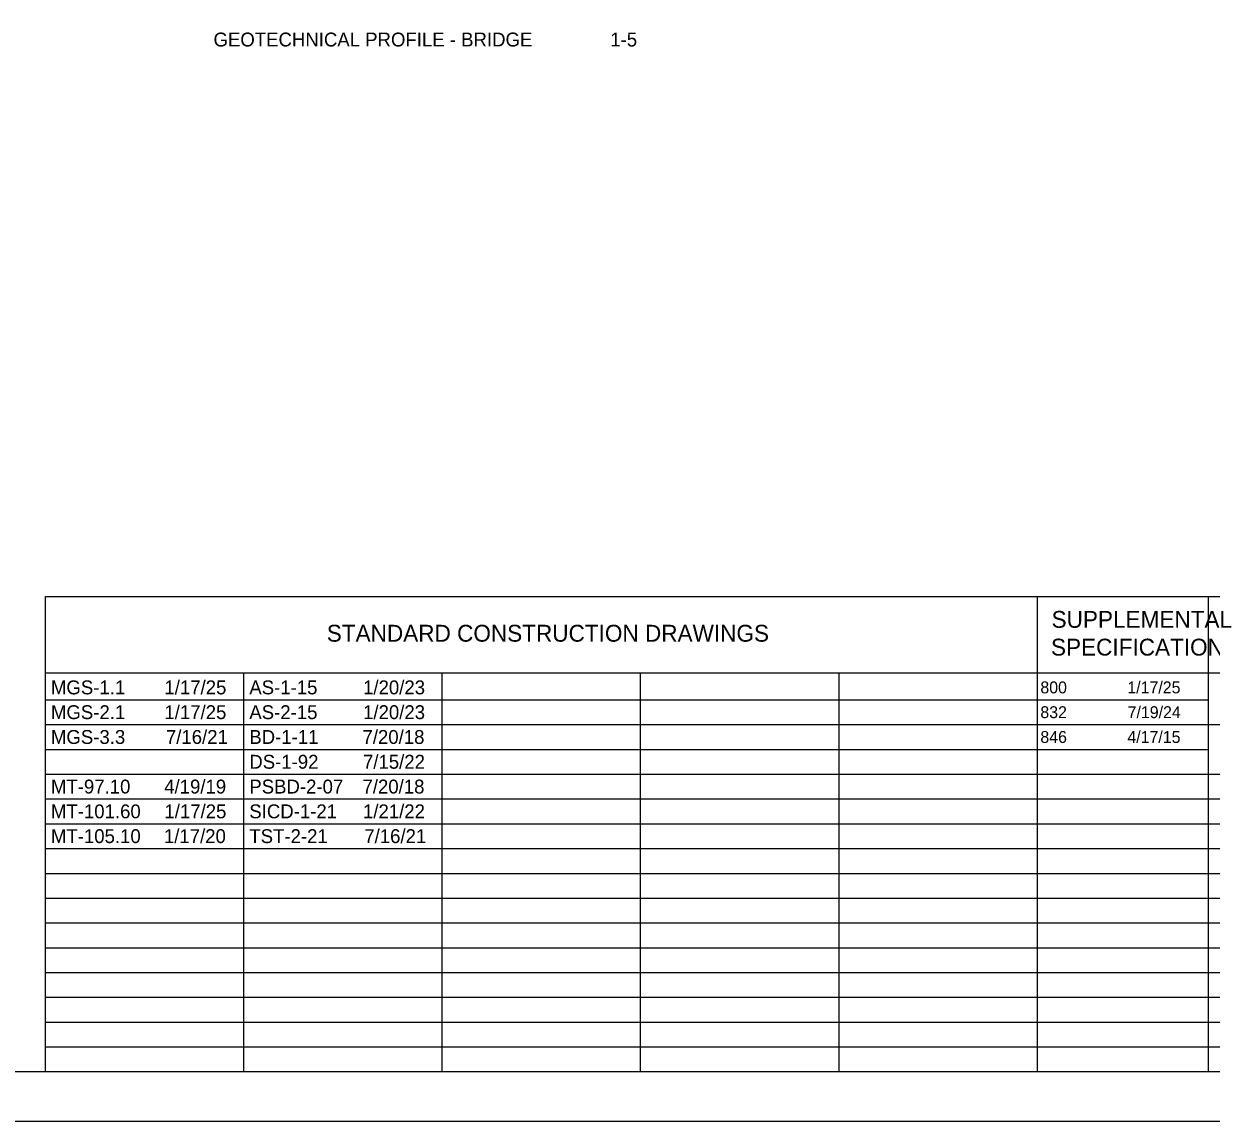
# Model space of a CAD drawing. Extents: x 0 to 34, y 0 to 22.
# Drawn here: x 9.93 to 21.9, y 0 to 11.07 of the extents above; entities that cross this region are included whole.
import ezdxf

# ---------------------------------------------------------------- set-up
doc = ezdxf.new("R2010")
doc.units = 0
for name, color, linetype in [('SH_Border', 7, 'Continuous'), ('SH_Cut_Line', 7, 'Continuous'), ('SH_Data', 7, 'Continuous'), ('SH_Text', 7, 'Continuous')]:
    doc.layers.add(name, color=color, linetype=linetype)

msp = doc.modelspace()

# ---------------------------------------------------------------- linework, layer by layer
at = {"layer": 'SH_Border'}
msp.add_lwpolyline([(1.5, 21.5), (33.5, 21.5), (33.5, 0.5), (1.5, 0.5)], close=True, dxfattribs=at)
at = {"layer": 'SH_Cut_Line'}
msp.add_lwpolyline([(0, 0), (34, 0), (34, 22), (0, 22)], close=True, dxfattribs=at)
at = {"layer": 'SH_Data'}
for p, q in [((10.15, 5.292), (23.6, 5.292)), ((10.15, 0.5), (10.15, 5.292)), ((20.15, 0.5), (20.15, 5.292)), ((21.875, 0.5), (21.875, 5.292)), ((10.15, 4.521), (23.6, 4.521)), ((12.15, 0.5), (12.15, 4.521)), ((14.15, 0.5), (14.15, 4.521)), ((16.15, 0.5), (16.15, 4.521)), ((18.15, 0.5), (18.15, 4.521)), ((10.15, 4.25), (21.875, 4.25)), ((10.15, 4), (23.6, 4)), ((10.15, 3.75), (21.875, 3.75)), ((10.15, 3.5), (23.6, 3.5)), ((10.15, 3.25), (23.6, 3.25)), ((10.15, 3), (23.6, 3)), ((10.15, 2.75), (23.6, 2.75)), ((10.15, 2.5), (23.6, 2.5)), ((10.15, 2.25), (23.6, 2.25)), ((10.15, 2), (23.6, 2)), ((10.15, 1.75), (23.6, 1.75)), ((10.15, 1.5), (23.6, 1.5)), ((10.15, 1.25), (23.6, 1.25)), ((10.15, 1), (23.6, 1)), ((10.15, 0.75), (23.6, 0.75))]:
    msp.add_line(p, q, dxfattribs=at)

# ---------------------------------------------------------------- texts
at = {"layer": 'SH_Text'}
for s, height, p in [('GEOTECHNICAL PROFILE - BRIDGE', 0.14, (11.844, 10.838)), ('1-5', 0.14, (15.844, 10.838)), ('SUPPLEMENTAL', 0.17, (20.293, 4.976)), ('STANDARD CONSTRUCTION DRAWINGS', 0.17, (12.986, 4.836)), ('SPECIFICATIONS', 0.17, (20.287, 4.696)), ('MGS-1.1', 0.14, (10.205, 4.305)), ('1/17/25', 0.14, (11.349, 4.305)), ('AS-1-15', 0.14, (12.205, 4.305)), ('1/20/23', 0.14, (13.352, 4.305)), ('800', 0.12, (20.18, 4.315)), ('1/17/25', 0.12, (21.057, 4.315)), ('MGS-2.1', 0.14, (10.205, 4.055)), ('1/17/25', 0.14, (11.349, 4.055)), ('AS-2-15', 0.14, (12.205, 4.055)), ('1/20/23', 0.14, (13.352, 4.055)), ('7/19/24', 0.12, (21.06, 4.065)), ('832', 0.12, (20.18, 4.065)), ('7/16/21', 0.14, (11.364, 3.805)), ('7/20/18', 0.14, (13.346, 3.805)), ('MGS-3.3', 0.14, (10.205, 3.805)), ('BD-1-11', 0.14, (12.205, 3.805)), ('846', 0.12, (20.18, 3.815)), ('4/17/15', 0.12, (21.057, 3.815)), ('DS-1-92', 0.14, (12.205, 3.555)), ('7/15/22', 0.14, (13.351, 3.555)), ('MT-97.10', 0.14, (10.205, 3.305)), ('4/19/19', 0.14, (11.347, 3.305)), ('PSBD-2-07', 0.14, (12.205, 3.305)), ('7/20/18', 0.14, (13.346, 3.305)), ('MT-101.60', 0.14, (10.205, 3.055)), ('1/17/25', 0.14, (11.349, 3.055)), ('SICD-1-21', 0.14, (12.205, 3.055)), ('1/21/22', 0.14, (13.351, 3.055)), ('MT-105.10', 0.14, (10.205, 2.805)), ('1/17/20', 0.14, (11.344, 2.805)), ('TST-2-21', 0.14, (12.205, 2.805)), ('7/16/21', 0.14, (13.364, 2.805))]:
    msp.add_text(s, height=height, dxfattribs=at).set_placement(p)

doc.saveas('drawing.dxf')
